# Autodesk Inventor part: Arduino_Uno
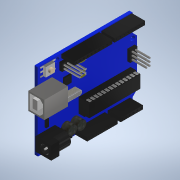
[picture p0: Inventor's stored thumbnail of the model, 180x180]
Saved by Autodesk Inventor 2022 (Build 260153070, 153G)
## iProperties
Created: 2016-11
Part Number: Arduino_Uno
Material: Steel
Document SubType Name: Modeling
Designer: Dimitris
Density: 7.85 g/cm^3
Appearance: Plate
Author: Dimitris
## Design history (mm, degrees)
sketch "Sketch1"
  geometry: L1 (-3.5, 0)-(-68, 0); L2 (-68.5, -0.5)-(-68.5, -53); L3 (-68, -53.5)-(-3.5, -53.5); L4 (-3, -53)-(-3, -50.5); L5 (-3, -50.5)-(-0.146, -47.646); L6 (0, -15.707)-(0, -47.293); L7 (-3, -0.5)-(-3, -12.5); L8 (-0.146, -15.354)-(-3, -12.5); A1 r 0.5 centre (-68, -53) between (-68.5, -53) and (-68, -53.5); A2 r 0.5 centre (-68, -0.5) between (-68, 0) and (-68.5, -0.5); A3 r 0.5 centre (-3.5, -53) between (-3.5, -53.5) and (-3, -53); A4 r 0.5 centre (-0.5, -47.293) between (-0.146, -47.646) and (0, -47.293); A5 r 0.5 centre (-0.5, -15.707) between (0, -15.707) and (-0.146, -15.354); A6 r 0.5 centre (-3.5, -0.5) between (-3, -0.5) and (-3.5, 0); 7 further points
  constraints: 16 end point, 12 point on circle, 12 point on line, 12 tangent, 6 centre point, 5 equal radius, 3 parallel, 3 perpendicular, 1 horizontal
  dimensions: "d1" = 53.5 distance of point (-68.5, -53.5) point (-68.5, 0); "d3" = 3 distance of point (-3, -53.5) L4.end; "d5" = 6 distance from line of point (0, -47.5) L3; "d6" = 3 distance between parallel lines of L6 L4; "d7" = 12.5 distance of point (-3, 0) L7.end; "d9" = 65.5 distance between parallel lines of L2 L7; "d10" = 65.5 distance between parallel lines of L2 L4; "d11" = 38 distance of L4.end L7.end (derived); "d12" = 32 distance of point (0, -15.5) point (0, -47.5) (derived); "d13" = 0.5 radius of A1
extrude "Extrusion1" new body sketch "Sketch1" distance "d14" = 2; taper "d15" = 0 deg
sketch "Sketch2"
  geometry: L1 (58.5, 1)-(64.7, 1); L2 (64.7, 1)-(64.7, 7.2); L3 (64.7, 7.2)-(58.5, 7.2); L4 (58.5, 7.2)-(58.5, 1); 1 further point
  constraints: 8 end point, 2 parallel, 1 horizontal, 1 perpendicular
  dimensions: "d16" = 6.2 distance of L3.end L2.end; "d17" = 6.2 distance of L2.end L1.end
extrude "Extrusion2" join sketch "Sketch2" distance "d18" = 2; taper "d19" = 0 deg
sketch "Sketch3"
  geometry: C1 r 1.57 at (61.6, 4.1); 1 further point
  constraints: 1 centre point
  dimensions: "d20" = 3.14 diameter of C1
extrude "Extrusion3" join sketch "Sketch3" distance "d21" = 1.5; taper "d22" = 0 deg
sketch "Sketch4"
  geometry: L1 (64.7, 7.2)-(64.7, 1) reference; L2 (64.72, 1)-(66.7, 1); L3 (66.7, 1)-(66.7, 1.8); L4 (66.7, 1.8)-(64.72, 1.8); L5 (64.7, 1.8)-(64.7, 1); L6 (64.72, 3.7)-(66.7, 3.7); L7 (66.7, 3.7)-(66.7, 4.5); L8 (66.7, 4.5)-(64.72, 4.5); L9 (64.7, 4.5)-(64.7, 3.7); L10 (64.72, 7.2)-(66.7, 7.2); L11 (66.7, 7.2)-(66.7, 6.4); L12 (66.7, 6.4)-(64.72, 6.4); L13 (64.7, 6.4)-(64.7, 7.2); L14 (58.48, 7.2)-(56.5, 7.2); L15 (56.5, 7.2)-(56.5, 6.4); L16 (56.5, 6.4)-(58.48, 6.4); L17 (58.5, 6.4)-(58.5, 7.2); L18 (58.48, 1)-(56.5, 1); L19 (56.5, 1)-(56.5, 1.8); L20 (56.5, 1.8)-(58.48, 1.8); L21 (58.5, 1.8)-(58.5, 1); L22 (58.5, 1)-(64.68, 1); L23 (64.72, 6.4)-(64.72, 7.2); L24 (64.72, 1)-(64.72, 1.8); L25 (64.72, 3.7)-(64.72, 4.5); L26 (58.48, 1)-(58.48, 1.8); L27 (58.48, 6.4)-(58.48, 7.2); 1 further point
  constraints: 52 end point, 10 parallel, 8 perpendicular, 6 horizontal, 2 point on line
  dimensions: "d23" = 2 distance of L5.start L3.end; "d24" = 0.8 distance of L3.end L2.end; "d25" = 2 distance of L9.start L7.end; "d26" = 0.8 distance of L7.end L6.end; "d27" = 0.8 distance of L10.end L11.end; "d28" = 2 distance of L17.start L15.end; "d29" = 0.02 distance of L18.start L21.end; "d31" = 0.02 distance of L2.start L1.end
extrude "Extrusion4" join sketch "Sketch4" distance "d32" = 0.4; taper "d33" = 0 deg
sketch "Sketch5"
  geometry: L1 (58.5, 11)-(74.8, 11); L2 (74.8, 11)-(74.8, 23); L3 (74.8, 23)-(58.5, 23); L4 (58.5, 23)-(58.5, 11); 1 further point
  constraints: 8 end point, 2 parallel, 1 horizontal, 1 perpendicular
  dimensions: "d34" = 16.3 distance of L3.end L2.end; "d35" = 12 distance of L2.end L1.end
extrude "Extrusion5" join sketch "Sketch5" distance "d36" = 11; taper "d37" = 0 deg
sketch "Sketch6"
  geometry: L1 (0, 0)-(12, 0) reference; L2 (12, 0)-(12, 11) reference; L3 (11, 8)-(11, 1); L4 (11, 1)-(1, 1); L5 (1, 1)-(1, 8); L6 (1, 1)-(1, 8); L7 (9, 10)-(11, 8); L8 (9, 10)-(3, 10); L9 (3, 10)-(1, 8); 1 further point
  constraints: 14 end point, 2 perpendicular
  dimensions: "d39" = 1 distance between parallel lines of L1 L4 (derived); "d40" = 1 distance between parallel lines of L2 L3 (derived); "d41" = 10 distance of L3.end L4.end (derived); "d43" = 7 distance of L5.end L4.end; "d44" = 6 distance of L7.start L8.end
extrude "Extrusion6" cut sketch "Sketch6" distance "d45" = 9; taper "d46" = 0 deg
sketch "Sketch7"
  geometry: L1 (3, 3)-(9, 3); L2 (9, 3)-(9, 6.2); L3 (9, 6.2)-(3, 6.2); L4 (3, 6.2)-(3, 3); 1 further point
  constraints: 8 end point, 2 parallel, 1 horizontal, 1 perpendicular
  dimensions: "d47" = 6 distance of L3.end L2.end; "d48" = 3.2 distance of L2.end L1.end
extrude "Extrusion7" join sketch "Sketch7" distance "d49" = 9; taper "d50" = 0 deg
sketch "Sketch8"
  geometry: L1 (3, 53)-(3, 50.5) reference; L2 (3.5, 0)-(68, 0) reference; L3 (68.5, 0.5)-(68.5, 11) reference; C1 r 1.5 at (3, 47.293); C2 r 1.5 at (3, 15.707); C3 r 1.5 at (52, 49.5); C4 r 1.5 at (55, 2.5); 1 further point
  constraints: 4 centre point, 1 point on line
  dimensions: "d51" = 3 diameter of C1; "d52" = 3 diameter of C2; "d53" = 3 diameter of C3; "d54" = 3 diameter of C4; "d79" = 2.5 distance from line of L2 C4.centre; "d80" = 13.5 distance from line of L3 C4.centre
hole "Hole1" sketch "Sketch8" at (3, 15.707), (3, 47.293), (55, 2.5), (52, 49.5) diameter "d55" = 3; stored, may be unused: countersink angle "d59" = 90 deg, drill point angle "d61" = 118 deg; dims "d56" = 6, "d57" = 4, "d58" = 2, "d60" = 8
sketch "Sketch9"
  geometry: L1 (56.5, 49.5)-(70.1, 49.5); L2 (70.1, 49.5)-(70.1, 40.5); L3 (70.1, 40.5)-(56.5, 40.5); L4 (56.5, 40.5)-(56.5, 49.5); 1 further point
  constraints: 8 end point, 2 parallel, 1 horizontal, 1 perpendicular
  dimensions: "d62" = 13.6 distance of L2.end L3.end; "d63" = 9 distance of L1.end L2.end
extrude "Extrusion8" join sketch "Sketch9" distance "d64" = 11; taper "d65" = 0 deg
sketch "Sketch10"
  geometry: C1 r 3 at (4.5, 6.5); 1 further point
  constraints: 1 centre point
  dimensions: "d66" = 6 diameter of C1
extrude "Extrusion9" cut sketch "Sketch10" distance "d67" = 8; taper "d68" = 0 deg
sketch "Sketch11"
  geometry: L1 (9, 0)-(0, 0) reference; L2 (9, 0)-(9, 11) reference; L3 (0, 11)-(9, 11) reference; L4 (0, 0)-(0, 11) reference; L5 (0, 6.5)-(0, 11); L6 (9, 11)-(0, 11); L7 (9, 11)-(9, 6.5); A1 r 4.5 centre (4.5, 6.5) between (9, 6.5) and (0, 6.5); 1 further point
  constraints: 6 end point, 2 collinear, 2 point on circle, 2 point on line, 2 tangent, 1 centre point
extrude "Extrusion10" cut sketch "Sketch11" distance "d69" = 8; taper "d70" = 0 deg
sketch "Sketch12"
  geometry: C1 r 3 at (0, 0) reference; C2 r 0.6 at (0, 0); 1 further point
  constraints: 1 centre point, 1 coincident
  dimensions: "d71" = 1.2 diameter of C2
extrude "Extrusion11" join sketch "Sketch12" distance "d72" = 8; taper "d73" = 0 deg
sketch "Sketch13"
  geometry: L1 (3.5, 0.5)-(24.5, 0.5); L2 (24.5, 0.5)-(24.5, 3); L3 (24.5, 3)-(3.5, 3); L4 (3.5, 3)-(3.5, 0.5); L5 (26, 0.5)-(52, 0.5); L6 (52, 0.5)-(52, 3); L7 (52, 3)-(26, 3); L8 (26, 3)-(26, 0.5); A1 r 0.5 centre (3.5, 0.5) between (3, 0.5) and (3.5, 0) reference; 1 further point
  constraints: 16 end point, 4 parallel, 2 horizontal, 2 perpendicular
  dimensions: "d74" = 21 distance of L3.end L2.end; "d75" = 2.5 distance of L2.end L1.end; "d76" = 26 distance of L7.end L6.end
extrude "Extrusion12" join sketch "Sketch13" distance "d77" = 9; taper "d78" = 0 deg
sketch "Sketch14" dims "d88" = 10
  geometry: L1 (3.5, 0.5)-(24.5, 0.5) reference; L2 (23.75, 2.25)-(23.75, 1.25); L3 (4.25, 1.25)-(4.25, 2.25); L4 (4.25, 1.25)-(5.25, 1.25); L5 (5.25, 1.25)-(5.25, 2.25); L6 (5.25, 2.25)-(4.25, 2.25); L7 (4.25, 2.25)-(4.25, 1.25); L8 (7.9, 1.25)-(7.9, 2.25); L9 (7.9, 2.25)-(6.9, 2.25); L10 (6.9, 2.25)-(6.9, 1.25); L11 (6.9, 1.25)-(7.9, 1.25); L12 (10.55, 1.25)-(10.55, 2.25); L13 (10.55, 2.25)-(9.55, 2.25); L14 (9.55, 2.25)-(9.55, 1.25); L15 (9.55, 1.25)-(10.55, 1.25); L16 (13.2, 1.25)-(13.2, 2.25); L17 (13.2, 2.25)-(12.2, 2.25); L18 (12.2, 2.25)-(12.2, 1.25); L19 (12.2, 1.25)-(13.2, 1.25); L20 (15.85, 1.25)-(15.85, 2.25); L21 (15.85, 2.25)-(14.85, 2.25); L22 (14.85, 2.25)-(14.85, 1.25); L23 (14.85, 1.25)-(15.85, 1.25); L24 (18.5, 1.25)-(18.5, 2.25); L25 (18.5, 2.25)-(17.5, 2.25); L26 (17.5, 2.25)-(17.5, 1.25); L27 (17.5, 1.25)-(18.5, 1.25); L28 (21.15, 1.25)-(21.15, 2.25); L29 (21.15, 2.25)-(20.15, 2.25); L30 (20.15, 2.25)-(20.15, 1.25); L31 (20.15, 1.25)-(21.15, 1.25); L32 (23.8, 1.25)-(23.8, 2.25); L33 (23.8, 2.25)-(22.8, 2.25); L34 (22.8, 2.25)-(22.8, 1.25); L35 (22.8, 1.25)-(23.8, 1.25); L36 (4.25, 2.25)-(5.25, 2.25); L37 (5.25, 1.25)-(4.25, 1.25); L38 (6.9, 2.25)-(7.9, 2.25); L39 (7.9, 1.25)-(6.9, 1.25); L40 (9.55, 2.25)-(10.55, 2.25); L41 (10.55, 1.25)-(9.55, 1.25); L42 (12.2, 2.25)-(13.2, 2.25); L43 (13.2, 1.25)-(12.2, 1.25); L44 (14.85, 2.25)-(15.85, 2.25); L45 (15.85, 1.25)-(14.85, 1.25); L46 (17.5, 2.25)-(18.5, 2.25); L47 (18.5, 1.25)-(17.5, 1.25); L48 (20.15, 2.25)-(21.15, 2.25); L49 (22.8, 2.25)-(23.75, 2.25); L50 (23.75, 1.25)-(22.8, 1.25); L51 (21.15, 1.25)-(20.15, 1.25); 1 further point
  constraints: 100 end point, 2 horizontal, 2 parallel, 1 perpendicular, 56 other
  dimensions: "d82" = 1 distance of L6.end L5.end; "d85" = 2.65 distance of L4.end L8.start
extrude "Extrusion13" cut sketch "Sketch14" distance "d90" = 1; taper "d91" = 0 deg
sketch "Sketch15" dims "d99" = 10
  geometry: L1 (26, 0.5)-(52, 0.5) reference; L2 (26.75, 1.25)-(26.75, 2.25); L3 (26.75, 2.25)-(27.75, 2.25); L4 (27.75, 2.25)-(27.75, 1.25); L5 (27.75, 1.25)-(26.75, 1.25); L6 (26.75, 1.25)-(26.75, 2.25); L7 (30.36, 2.25)-(30.36, 1.25); L8 (29.36, 2.25)-(30.36, 2.25); L9 (29.36, 1.25)-(29.36, 2.25); L10 (30.36, 1.25)-(29.36, 1.25); L11 (32.97, 2.25)-(32.97, 1.25); L12 (31.97, 2.25)-(32.97, 2.25); L13 (31.97, 1.25)-(31.97, 2.25); L14 (32.97, 1.25)-(31.97, 1.25); L15 (35.58, 2.25)-(35.58, 1.25); L16 (34.58, 2.25)-(35.58, 2.25); L17 (34.58, 1.25)-(34.58, 2.25); L18 (35.58, 1.25)-(34.58, 1.25); L19 (38.19, 2.25)-(38.19, 1.25); L20 (37.19, 2.25)-(38.19, 2.25); L21 (37.19, 1.25)-(37.19, 2.25); L22 (38.19, 1.25)-(37.19, 1.25); L23 (40.8, 2.25)-(40.8, 1.25); L24 (39.8, 2.25)-(40.8, 2.25); L25 (39.8, 1.25)-(39.8, 2.25); L26 (40.8, 1.25)-(39.8, 1.25); L27 (43.41, 2.25)-(43.41, 1.25); L28 (42.41, 2.25)-(43.41, 2.25); L29 (42.41, 1.25)-(42.41, 2.25); L30 (43.41, 1.25)-(42.41, 1.25); L31 (46.02, 2.25)-(46.02, 1.25); L32 (45.02, 2.25)-(46.02, 2.25); L33 (45.02, 1.25)-(45.02, 2.25); L34 (46.02, 1.25)-(45.02, 1.25); L35 (48.63, 2.25)-(48.63, 1.25); L36 (47.63, 2.25)-(48.63, 2.25); L37 (47.63, 1.25)-(47.63, 2.25); L38 (48.63, 1.25)-(47.63, 1.25); L39 (51.24, 2.25)-(51.24, 1.25); L40 (50.24, 2.25)-(51.24, 2.25); L41 (50.24, 1.25)-(50.24, 2.25); L42 (51.24, 1.25)-(50.24, 1.25); L43 (50.24, 2.25)-(51.24, 2.25); L44 (51.24, 1.25)-(50.24, 1.25); L45 (47.63, 2.25)-(48.63, 2.25); L46 (48.63, 1.25)-(47.63, 1.25); L47 (45.02, 2.25)-(46.02, 2.25); L48 (46.02, 1.25)-(45.02, 1.25); L49 (43.41, 1.25)-(42.41, 1.25); L50 (42.41, 2.25)-(43.41, 2.25); L51 (40.8, 1.25)-(39.8, 1.25); L52 (39.8, 2.25)-(40.8, 2.25); L53 (38.19, 1.25)-(37.19, 1.25); L54 (37.19, 2.25)-(38.19, 2.25); L55 (34.58, 2.25)-(35.58, 2.25); L56 (35.58, 1.25)-(34.58, 1.25); L57 (32.97, 1.25)-(31.97, 1.25); L58 (31.97, 2.25)-(32.97, 2.25); L59 (26.75, 2.25)-(27.75, 2.25); L60 (29.36, 2.25)-(30.36, 2.25); L61 (30.36, 1.25)-(29.36, 1.25); L62 (27.75, 1.25)-(26.75, 1.25); 1 further point
  constraints: 122 end point, 2 horizontal, 2 parallel, 1 perpendicular, 72 other
  dimensions: "d93" = 1 distance of L4.end L5.end; "d96" = 2.61 distance of L3.end L7.start
extrude "Extrusion14" cut sketch "Sketch15" distance "d101" = 1; taper "d102" = 0 deg
sketch "Sketch16"
  geometry: L1 (5, 52.5)-(20.3, 52.5); L2 (20.3, 52.5)-(20.3, 50); L3 (20.3, 50)-(5, 50); L4 (5, 50)-(5, 52.5); L5 (22.3, 52.5)-(43.3, 52.5); L6 (43.3, 52.5)-(43.3, 50); L7 (43.3, 50)-(22.3, 50); L8 (22.3, 50)-(22.3, 52.5); 1 further point
  constraints: 16 end point, 4 parallel, 2 horizontal, 2 perpendicular
  dimensions: "d103" = 15.3 distance of L2.end L3.end; "d104" = 2.5 distance of L1.end L2.end; "d105" = 21 distance of L6.end L7.end
extrude "Extrusion15" join sketch "Sketch16" distance "d106" = 9; taper "d107" = 0 deg
sketch "Sketch17" dims "d115" = 10
  geometry: L1 (22.3, 52.5)-(22.3, 50) reference; L2 (22.3, 50)-(43.3, 50) reference; L3 (43.3, 50)-(43.3, 52.5) reference; L4 (42.55, 51.75)-(42.55, 50.75); L5 (42.55, 50.75)-(23.05, 50.75); L6 (23.05, 50.75)-(23.05, 51.75); L7 (23.05, 51.75)-(24.05, 51.75); L8 (24.05, 51.75)-(24.05, 50.75); L9 (24.05, 50.75)-(23.05, 50.75); L10 (23.05, 50.75)-(23.05, 51.75); L11 (26.7, 50.75)-(25.7, 50.75); L12 (25.7, 50.75)-(25.7, 51.75); L13 (25.7, 51.75)-(26.7, 51.75); L14 (26.7, 51.75)-(26.7, 50.75); L15 (29.35, 50.75)-(28.35, 50.75); L16 (28.35, 50.75)-(28.35, 51.75); L17 (28.35, 51.75)-(29.35, 51.75); L18 (29.35, 51.75)-(29.35, 50.75); L19 (32, 50.75)-(31, 50.75); L20 (31, 50.75)-(31, 51.75); L21 (31, 51.75)-(32, 51.75); L22 (32, 51.75)-(32, 50.75); L23 (34.65, 50.75)-(33.65, 50.75); L24 (33.65, 50.75)-(33.65, 51.75); L25 (33.65, 51.75)-(34.65, 51.75); L26 (34.65, 51.75)-(34.65, 50.75); L27 (37.3, 50.75)-(36.3, 50.75); L28 (36.3, 50.75)-(36.3, 51.75); L29 (36.3, 51.75)-(37.3, 51.75); L30 (37.3, 51.75)-(37.3, 50.75); L31 (39.95, 50.75)-(38.95, 50.75); L32 (38.95, 50.75)-(38.95, 51.75); L33 (38.95, 51.75)-(39.95, 51.75); L34 (39.95, 51.75)-(39.95, 50.75); L35 (42.6, 50.75)-(41.6, 50.75); L36 (41.6, 50.75)-(41.6, 51.75); L37 (41.6, 51.75)-(42.6, 51.75); L38 (42.6, 51.75)-(42.6, 50.75); L39 (41.6, 51.75)-(42.55, 51.75); L40 (38.95, 51.75)-(39.95, 51.75); L41 (36.3, 51.75)-(37.3, 51.75); L42 (33.65, 51.75)-(34.65, 51.75); L43 (31, 51.75)-(32, 51.75); L44 (28.35, 51.75)-(29.35, 51.75); L45 (23.05, 51.75)-(24.05, 51.75); L46 (25.7, 51.75)-(26.7, 51.75); 1 further point
  constraints: 86 end point, 2 horizontal, 2 parallel, 1 perpendicular, 1 point on line, 58 other
  dimensions: "d109" = 1 distance of L8.end L9.end; "d112" = 2.65 distance of L8.end L11.start
extrude "Extrusion16" cut sketch "Sketch17" distance "d117" = 1; taper "d118" = 0 deg
sketch "Sketch18" dims "d126" = 10
  geometry: L1 (5, 52.5)-(5, 50) reference; L2 (5, 50)-(20.3, 50) reference; L3 (19.55, 50.75)-(5.75, 50.75); L4 (5.75, 50.75)-(5.75, 51.75); L5 (5.75, 51.75)-(6.75, 51.75); L6 (6.75, 51.75)-(6.75, 50.75); L7 (6.75, 50.75)-(5.75, 50.75); L8 (5.75, 50.75)-(5.75, 51.75); L9 (8.35, 51.75)-(9.35, 51.75); L10 (9.35, 51.75)-(9.35, 50.75); L11 (9.35, 50.75)-(8.35, 50.75); L12 (8.35, 50.75)-(8.35, 51.75); L13 (10.95, 51.75)-(11.95, 51.75); L14 (11.95, 51.75)-(11.95, 50.75); L15 (11.95, 50.75)-(10.95, 50.75); L16 (10.95, 50.75)-(10.95, 51.75); L17 (13.55, 51.75)-(14.55, 51.75); L18 (14.55, 51.75)-(14.55, 50.75); L19 (14.55, 50.75)-(13.55, 50.75); L20 (13.55, 50.75)-(13.55, 51.75); L21 (16.15, 51.75)-(17.15, 51.75); L22 (17.15, 51.75)-(17.15, 50.75); L23 (17.15, 50.75)-(16.15, 50.75); L24 (16.15, 50.75)-(16.15, 51.75); L25 (18.75, 51.75)-(19.75, 51.75); L26 (19.75, 51.75)-(19.75, 50.75); L27 (19.75, 50.75)-(18.75, 50.75); L28 (18.75, 50.75)-(18.75, 51.75); L29 (18.75, 51.75)-(19.55, 51.75); L30 (16.15, 51.75)-(17.15, 51.75); L31 (13.55, 51.75)-(14.55, 51.75); L32 (10.95, 51.75)-(11.95, 51.75); L33 (5.75, 51.75)-(6.75, 51.75); L34 (8.35, 51.75)-(9.35, 51.75); 1 further point
  constraints: 64 end point, 2 horizontal, 2 parallel, 1 perpendicular, 1 point on line, 41 other
  dimensions: "d120" = 1 distance of L6.end L7.end; "d123" = 2.6 distance of L4.end L9.start
extrude "Extrusion17" cut sketch "Sketch18" distance "d128" = 1; taper "d129" = 0 deg
sketch "Sketch19"
  geometry: L1 (4.5, 42)-(40.1, 42); L2 (40.1, 42)-(40.1, 32); L3 (40.1, 32)-(4.5, 32); L4 (4.5, 32)-(4.5, 42); 1 further point
  constraints: 8 end point, 2 parallel, 1 horizontal, 1 perpendicular
  dimensions: "d130" = 35.6 distance of L2.end L3.end; "d131" = 10 distance of L1.end L2.end
extrude "Extrusion18" join sketch "Sketch19" distance "d132" = 4; taper "d133" = 0 deg
sketch "Sketch20"
  geometry: L1 (4.6, 32.5)-(40, 32.5); L2 (40, 32.5)-(40, 41.5); L3 (40, 41.5)-(4.6, 41.5); L4 (4.6, 41.5)-(4.6, 32.5); 1 further point
  constraints: 8 end point, 2 parallel, 1 horizontal, 1 perpendicular
  dimensions: "d134" = 35.4 distance of L3.end L2.end; "d135" = 9 distance of L2.end L1.end
extrude "Extrusion19" join sketch "Sketch20" distance "d136" = 3; taper "d137" = 0 deg
chamfer "Chamfer1" distance "d138" = 0.2; stored, may be unused: second distance "d139" = 2, angle "d140" = 45 deg; dims "d207" = 3.25
sketch "Sketch21"
  geometry: L1 (35, 0)-(0, 0) reference; L2 (0.5, 0)-(2, 0); L3 (2, 0)-(2, 2.5); L4 (2, 2.5)-(0.5, 2.5); L5 (0.5, 2.5)-(0.5, 0); 1 further point
  constraints: 8 end point, 2 parallel, 1 horizontal, 1 perpendicular, 1 point on line
  dimensions: "d141" = 1.5 distance of L4.end L3.end; "d142" = 2.5 distance of L3.end L2.end
extrude "Extrusion20" join sketch "Sketch21" distance "d143" = 0.3; taper "d144" = 0 deg
pattern_linear "Rectangular Pattern1" dims "d147" = 2.48
workplane "Work Plane1"
mirror "Mirror1"
sketch "Sketch22"
  geometry: L1 (0, 47.293)-(0, 15.707) reference; L2 (3.5, 0)-(68, 0) reference; C1 r 3.1 at (43, 45); C2 r 3.1 at (49.3, 45); 1 further point
  constraints: 2 centre point
  dimensions: "d148" = 6.2 diameter of C1; "d149" = 6.2 diameter of C2; "d150" = 6.3 distance of C2.centre C1.centre; "d151" = 45 distance from line of L2 C1.centre; "d152" = 43 distance from line of L1 C1.centre
extrude "Extrusion21" join sketch "Sketch22" distance "d153" = 5; taper "d154" = 0 deg
sketch "Sketch23"
  geometry: L1 (1.75, 20)-(6.75, 20); L2 (6.75, 20)-(6.75, 27.5); L3 (6.75, 27.5)-(1.75, 27.5); L4 (1.75, 27.5)-(1.75, 20); L5 (53.5, 4.5)-(46, 4.5); L6 (46, 4.5)-(46, 9.5); L7 (46, 9.5)-(53.5, 9.5); L8 (53.5, 9.5)-(53.5, 4.5); 1 further point
  constraints: 16 end point, 4 parallel, 2 horizontal, 2 perpendicular
  dimensions: "d155" = 5 distance of L3.end L2.end; "d156" = 7.5 distance of L2.end L1.end; "d157" = 7.5 distance of L6.end L7.end; "d158" = 5 distance of L5.end L6.end
extrude "Extrusion22" join sketch "Sketch23" distance "d159" = 2; taper "d160" = 0 deg
sketch "Sketch24"
  geometry: L1 (46, 20)-(51, 20); L2 (51, 20)-(51, 15); L3 (51, 15)-(46, 15); L4 (46, 15)-(46, 20); 1 further point
  constraints: 8 end point, 2 parallel, 1 horizontal, 1 perpendicular
  dimensions: "d161" = 5 distance of L2.end L3.end; "d162" = 5 distance of L1.end L2.end
extrude "Extrusion23" join sketch "Sketch24" distance "d163" = 1; taper "d164" = 0 deg
sketch "Sketch25"
  geometry: L1 (45.15, 52.5)-(50.15, 52.5); L2 (50.15, 52.5)-(50.15, 50); L3 (50.15, 50)-(45.15, 50); L4 (45.15, 50)-(45.15, 52.5); 1 further point
  constraints: 8 end point, 2 parallel, 1 horizontal, 1 perpendicular
  dimensions: "d165" = 5 distance of L2.end L3.end
extrude "Extrusion24" join sketch "Sketch25" distance "d166" = 0.5; taper "d167" = 0 deg
sketch "Sketch26"
  geometry: L1 (50.15, 52.5)-(45.15, 52.5) reference; L2 (45.15, 50)-(50.15, 50) reference; L3 (46.15, 52.5)-(49.15, 52.5); L4 (49.15, 52.5)-(49.15, 50); L5 (49.15, 50)-(46.15, 50); L6 (46.15, 50)-(46.15, 52.5); 1 further point
  constraints: 8 end point, 2 parallel, 2 point on line, 1 horizontal, 1 perpendicular
  dimensions: "d168" = 3 distance of L4.end L5.end
extrude "Extrusion25" join sketch "Sketch26" distance "d169" = 1; taper "d170" = 0 deg
sketch "Sketch27"
  geometry: L1 (63.5, 38.5)-(61.5, 38.5); L2 (61.5, 38.5)-(61.5, 33.5); L3 (61.5, 33.5)-(63.5, 33.5); L4 (63.5, 33.5)-(63.5, 38.5); 1 further point
  constraints: 8 end point, 2 parallel, 1 horizontal, 1 perpendicular
  dimensions: "d171" = 2 distance of L3.end L2.end; "d172" = 5 distance of L2.end L1.end
extrude "Extrusion26" join sketch "Sketch27" distance "d173" = 1; taper "d174" = 0 deg
sketch "Sketch28"
  geometry: L1 (1.75, 20)-(6.75, 20) reference; L2 (6.75, 27.5)-(1.75, 27.5) reference; L3 (1.75, 27.5)-(1.75, 20) reference; L4 (2.75, 26.5)-(5.75, 26.5); L5 (5.75, 21)-(2.75, 21); L6 (2.75, 21)-(2.75, 26.5); L7 (2.75, 26.5)-(3.55, 26.5); L8 (3.55, 26.5)-(3.55, 25.7); L9 (3.55, 25.7)-(2.75, 25.7); L10 (2.75, 25.7)-(2.75, 26.5); L11 (3.55, 23.35)-(2.75, 23.35); L12 (2.75, 23.35)-(2.75, 24.15); L13 (3.55, 24.15)-(3.55, 23.35); L14 (2.75, 24.15)-(3.55, 24.15); L15 (3.55, 21)-(2.75, 21); L16 (2.75, 21)-(2.75, 21.8); L17 (3.55, 21.8)-(3.55, 21); L18 (2.75, 21.8)-(3.55, 21.8); L19 (5.75, 25.7)-(4.95, 25.7); L20 (4.95, 25.7)-(4.95, 26.5); L21 (5.75, 26.5)-(5.75, 25.7); L22 (4.95, 26.5)-(5.75, 26.5); L23 (5.75, 23.35)-(4.95, 23.35); L24 (4.95, 23.35)-(4.95, 24.15); L25 (5.75, 24.15)-(5.75, 23.35); L26 (4.95, 24.15)-(5.75, 24.15); L27 (5.75, 21)-(4.95, 21); L28 (4.95, 21)-(4.95, 21.8); L29 (5.75, 21.8)-(5.75, 21); L30 (4.95, 21.8)-(5.75, 21.8); L31 (5.75, 26.5)-(5.75, 25.7); L32 (5.75, 24.15)-(5.75, 23.35); L33 (5.75, 21.8)-(5.75, 21); 1 further point
  constraints: 60 end point, 2 horizontal, 2 parallel, 1 perpendicular, 1 vertical, 41 other
  dimensions: "d175" = 1 distance between parallel lines of L2 L4; "d180" = 2.35 distance of L8.end L11.start; "d183" = 2.2 distance of L8.end L19.start
extrude "Extrusion27" join sketch "Sketch28" distance "d186" = 10; taper "d187" = 0 deg
sketch "Sketch29"
  geometry: L1 (43.3, 24.454)-(53.3, 24.454); L2 (53.3, 27.954)-(43.3, 27.954); A1 r 1.75 centre (43.3, 26.204) between (43.3, 27.954) and (43.3, 24.454); A2 r 1.75 centre (53.3, 26.204) between (53.3, 24.454) and (53.3, 27.954); 1 further point
  constraints: 4 end point, 4 point on circle, 2 centre point, 1 horizontal, 1 parallel
  dimensions: "d188" = 10 distance of L2.end L2.start; "d189" = 3.5 distance of L2.start L1.end
extrude "Extrusion28" join sketch "Sketch29" distance "d190" = 4; taper "d191" = 0 deg
fillet "Fillet1" dims "d192" = 0.5, "d207" = 3.25
sketch "Sketch30"
  geometry: L1 (46, 4.5)-(53.5, 4.5) reference; L2 (53.5, 4.5)-(53.5, 9.5) reference; L3 (53.5, 9.5)-(46, 9.5) reference; L4 (46, 9.5)-(46, 4.5) reference; L5 (47, 8.5)-(52.5, 8.5); L6 (52.5, 8.5)-(52.5, 5.5); L7 (52.5, 5.5)-(47, 5.5); L8 (47, 5.5)-(47, 8.5); L9 (47, 5.5)-(47.8, 5.5); L10 (47.8, 5.5)-(47.8, 6.3); L11 (47.8, 6.3)-(47, 6.3); L12 (47, 6.3)-(47, 5.5); L13 (50.15, 5.5)-(50.15, 6.3); L14 (50.15, 6.3)-(49.35, 6.3); L15 (49.35, 6.3)-(49.35, 5.5); L16 (49.35, 5.5)-(50.15, 5.5); L17 (52.5, 5.5)-(52.5, 6.3); L18 (52.5, 6.3)-(51.7, 6.3); L19 (51.7, 6.3)-(51.7, 5.5); L20 (51.7, 5.5)-(52.5, 5.5); L21 (47.8, 7.7)-(47.8, 8.5); L22 (47.8, 8.5)-(47, 8.5); L23 (47, 8.5)-(47, 7.7); L24 (47, 7.7)-(47.8, 7.7); L25 (50.15, 7.7)-(50.15, 8.5); L26 (50.15, 8.5)-(49.35, 8.5); L27 (49.35, 8.5)-(49.35, 7.7); L28 (49.35, 7.7)-(50.15, 7.7); L29 (52.5, 7.7)-(52.5, 8.5); L30 (52.5, 8.5)-(51.7, 8.5); L31 (51.7, 8.5)-(51.7, 7.7); L32 (51.7, 7.7)-(52.5, 7.7); 1 further point
  constraints: 56 end point, 2 horizontal, 2 parallel, 1 perpendicular, 1 vertical, 43 other
  dimensions: "d193" = 1 distance between parallel lines of L3 L5; "d194" = 0.8 distance of L11.end L10.end; "d195" = 0.8 distance of L10.end L9.end; "d198" = 2.35 distance of L9.end L13.start; "d201" = 2.2 distance of L9.end L21.start
extrude "Extrusion29" join sketch "Sketch30" distance "d204" = 10; taper "d205" = 0 deg
sketch "Sketch31"
  geometry: L1 (39, 11)-(35.75, 11); L2 (35.75, 11)-(35.75, 12.5); L3 (35.75, 12.5)-(39, 12.5); L4 (39, 12.5)-(39, 11); L5 (39, 17.207)-(35.75, 17.207); L6 (35.75, 17.207)-(35.75, 18.707); L7 (35.75, 18.707)-(39, 18.707); L8 (39, 18.707)-(39, 17.207); L9 (39, 20)-(35.75, 20); L10 (35.75, 20)-(35.75, 21.5); L11 (35.75, 21.5)-(39, 21.5); L12 (39, 21.5)-(39, 20); 1 further point
  constraints: 24 end point, 6 parallel, 3 horizontal, 3 perpendicular
  dimensions: "d206" = 1.5 distance of L1.end L2.end; "d207" = 3.25 distance of L1.start L1.end; "d208" = 3.25 distance of L6.end L7.end; "d209" = 1.5 distance of L5.end L6.end; "d210" = 1.5 distance of L9.end L10.end
extrude "Extrusion30" join sketch "Sketch31" distance "d211" = 0.2; taper "d212" = 0 deg
sketch "Sketch32"
  geometry: L1 (35.75, 17.207)-(35.75, 18.707) reference; L2 (39, 18.707)-(39, 17.207) reference; L3 (35.75, 11)-(35.75, 12.5) reference; L4 (39, 12.5)-(39, 11) reference; L5 (35.75, 20)-(35.75, 21.5) reference; L6 (39, 21.5)-(39, 20) reference; L7 (35.75, 21.3)-(34.95, 21.3); L8 (34.95, 21.3)-(34.95, 20.2); L9 (34.95, 20.2)-(35.75, 20.2); L10 (35.75, 20.2)-(35.75, 21.3); L11 (39, 21.3)-(39.8, 21.3); L12 (39.8, 21.3)-(39.8, 20.2); L13 (39.8, 20.2)-(39, 20.2); L14 (39, 20.2)-(39, 21.3); L15 (35.75, 18.407)-(34.83, 18.407); L16 (34.83, 18.407)-(34.83, 17.307); L17 (34.83, 17.307)-(35.75, 17.307); L18 (35.75, 17.307)-(35.75, 18.407); L19 (39, 18.407)-(39.8, 18.407); L20 (39.8, 18.407)-(39.8, 17.307); L21 (39.8, 17.307)-(39, 17.307); L22 (39, 17.307)-(39, 18.407); L23 (35.75, 12.2)-(34.95, 12.2); L24 (34.95, 12.2)-(34.95, 11.1); L25 (34.95, 11.1)-(35.75, 11.1); L26 (35.75, 11.1)-(35.75, 12.2); L27 (39, 12.2)-(39.8, 12.2); L28 (39.8, 12.2)-(39.8, 11.1); L29 (39.8, 11.1)-(39, 11.1); L30 (39, 11.1)-(39, 12.2); 1 further point
  constraints: 48 end point, 12 parallel, 6 horizontal, 6 perpendicular, 6 point on line
  dimensions: "d213" = 0.8 distance of L9.end L8.end; "d214" = 1.1 distance of L8.end L7.end; "d215" = 0.8 distance of L12.end L13.end; "d216" = 1.1 distance of L16.end L15.end; "d217" = 1.1 distance of L24.end L23.end
extrude "Extrusion31" join sketch "Sketch32" distance "d218" = 0.1; taper "d219" = 0 deg
node "Direct Edit1"
node "Direct Edit2"
node "Direct Edit3"
node "Direct Edit4"
node "Direct Edit5"
body "Solid1"
feature "Rotate1" dims "d220" = -90 deg
feature "Rotate2" dims "d221" = -90 deg
feature "Scale1"
feature "Rotate3" dims "d225" = 90 deg
feature "Scale2"
other parameters: "d30" = 90 deg, "d81" = 0.75, "d92" = 0.75, "d108" = 0.75, "d119" = 0.75, "d222" = 3.77904
